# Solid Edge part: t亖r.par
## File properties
Author: Kasutaja
Template: Iso Metric Part.par
Last saved by: Kasutaja
Revision: 4
Application: Solid Edge
Accuracy: 0,990
Username: Kasutaja
Face Style: Model Default
Fill Style: Normal
Coef. of Thermal Exp: 0.0
Thermal Conductivity: 0.0
Specific Heat: 0.0
Modulus of Elasticity: 0.0
Poisson's Ratio: 0.0
Yield Stress: 0.0
Ultimate Stress: 0.0
Elongation: 0.0
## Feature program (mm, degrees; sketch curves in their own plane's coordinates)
sketch for "unnamed Protrusion 1" plane through (0, 0, 0) normal (0, -1, 0) x-axis (1, 0, 0)
  circle centre (0, 32.5935) radius 2
extrude "unnamed Protrusion 1" add finite 5 along +normal
sketch for "ExtrudedProtrusion_2" plane through (0, 0, 32.5935) normal (0, 1, 0) x-axis (1, 0, 0)
  circle centre (0, 0) radius 2.5
extrude "ExtrudedProtrusion_2" add finite 50 along +normal
fillet "Round_1" radius 2
fillet "Round_2" radius 2
sketch for "ExtrudedProtrusion_6" plane through (0, -5, 32.5935) normal (0, -1, 0) x-axis (1, 0, 0)
  line (-7.5, -60) -> (-7.5, 60)
  line (-7.5, 60) -> (-4, 60)
  line (-4, 100) -> (-4, 60)
  line (4, 100) -> (-4, 100)
  line (4, 60) -> (4, 100)
  line (4, 60) -> (7.5, 60)
  line (7.5, 60) -> (7.5, -60)
  arc centre (-7.5, -60) radius 15 from (7.5, -60) to (-7.5, -75) cw
  line (-7.5, -60) -> (-7.5, -75)
extrude "ExtrudedProtrusion_6" add finite 6 along -normal
chamfer "Chamfer_2" setback 3
sketch for "ExtrudedProtrusion_7" plane through (0, -5, 32.5935) normal (0, -1, 0) x-axis (1, 0, 0)
  circle centre (0, 89.2867) radius 2.5
extrude "ExtrudedProtrusion_7" add finite 40 along -normal
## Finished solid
Body 1: solid body, 18 faces, 35 edges, 19 vertices.
  Faces by surface: plane 12, cone 2, cylinder 2, torus 2
  Edges by curve: line 26, circle 9
Bounding box of the edges (mm; curved faces can reach further): 15.000 x 55.000 x 175.000, from (-7.5, -5, -42.4065) to (7.5, 50, 132.5935).
Cylindrical faces by radius (mm): R2.5 x2
Conical faces (half-angle, radius in mm at the cone's reference point): 45 deg R12 x1, 45 deg R15 x1
Toroidal faces (ring radius, tube radius in mm): R0.5 r2 x2
Planar faces by outward normal: +x 1, +y 3, +z 3, -x 2, -y 1, oblique 2
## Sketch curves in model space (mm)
line (-7.5, -5, -27.4065) -> (-7.5, -5, -22.4065)
line (-7.5, -5, 32.5935) -> (7.5, -5, 32.5935)
circle centre (0, -5, 121.8802) radius 2.5
line (-7.5, -5, -27.4065) -> (-7.5, -5, -42.4065)
arc centre (-7.5, -5, -27.4065) radius 15 from (7.5, -5, -27.4065) through (2.7936, -5, -38.3171) to (-7.5, -5, -42.4065)
line (7.5, -5, 92.5935) -> (7.5, -5, -27.4065)
line (4, -5, 92.5935) -> (7.5, -5, 92.5935)
line (4, -5, 92.5935) -> (4, -5, 132.5935)
line (4, -5, 132.5935) -> (-4, -5, 132.5935)
line (-4, -5, 132.5935) -> (-4, -5, 92.5935)
line (-7.5, -5, -27.4065) -> (-7.5, -5, 92.5935)
line (-7.5, -5, 92.5935) -> (-4, -5, 92.5935)
circle centre (0, 0, 32.5935) radius 2.5
circle centre (0, 0, 32.5935) radius 2
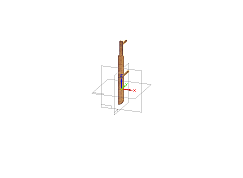
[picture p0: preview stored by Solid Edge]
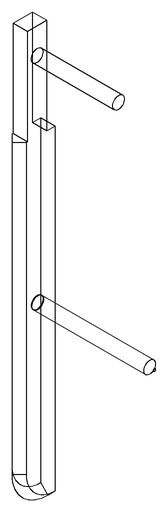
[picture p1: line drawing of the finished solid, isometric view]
